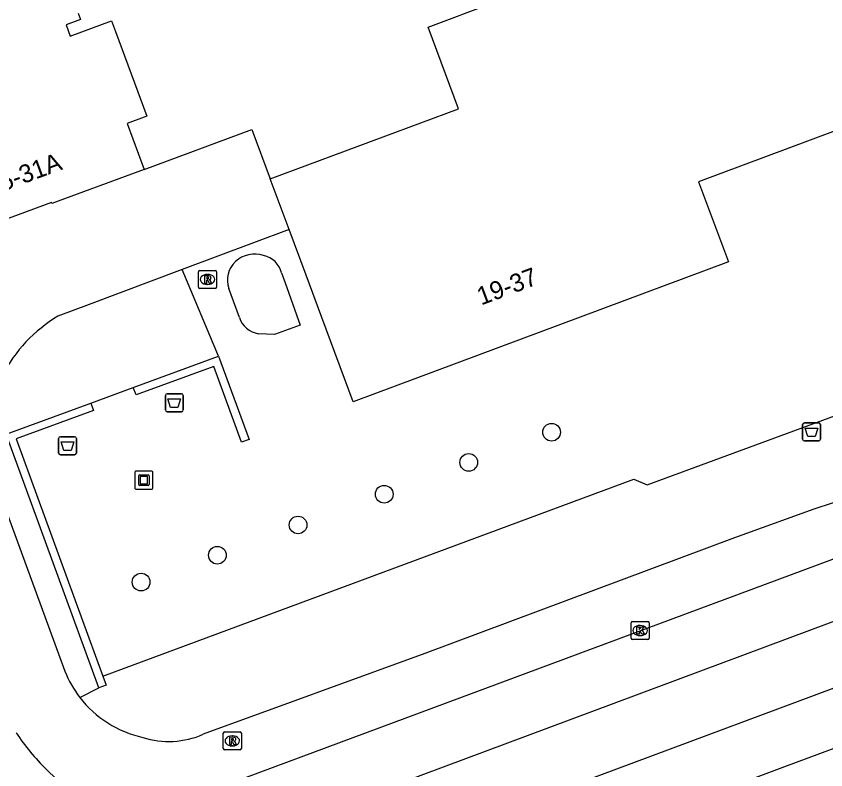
# Model space of a CAD drawing. Extents: x 160806 to 161707, y 383697 to 384148.
# Drawn here: x 161051.44 to 161096.26, y 383880.08 to 383921.78 of the extents above; entities that cross this region are included whole.
import ezdxf

# ---------------------------------------------------------------- set-up
doc = ezdxf.new("R2010")
doc.units = 0
for name, color, linetype in [('IMGEO_Afvalbak', 7, 'Continuous'), ('IMGEO_Boom', 7, 'Continuous'), ('IMGEO_Kolk', 7, 'Continuous'), ('IMGEO_Kunstobject', 7, 'Continuous'), ('IMGEO_Muur', 7, 'Continuous'), ('IMGEO_Pand', 7, 'Continuous'), ('IMGEO_Pand_nummerreeks', 7, 'Continuous'), ('IMGEO_Rijbaan_lokaal_gesloten', 7, 'Continuous'), ('IMGEO_Rijbaan_lokaal_open', 7, 'Continuous'), ('IMGEO_Rioolput', 7, 'Continuous'), ('IMGEO_Voetpad_open', 7, 'Continuous')]:
    doc.layers.add(name, color=color, linetype=linetype)

msp = doc.modelspace()

# ---------------------------------------------------------------- linework, layer by layer
at = {"layer": 'IMGEO_Afvalbak'}
for p, q in [((161059.699, 383899.988), (161059.699, 383900.788)), ((161059.699, 383900.788), (161059.699, 383899.988)), ((161059.799, 383900.888), (161060.589, 383900.888)), ((161060.589, 383900.888), (161059.799, 383900.888)), ((161060.689, 383900.788), (161060.689, 383899.988)), ((161060.689, 383899.988), (161060.689, 383900.788)), ((161060.589, 383899.888), (161059.799, 383899.888)), ((161059.799, 383899.888), (161060.589, 383899.888)), ((161094.972, 383898.377), (161094.972, 383899.177)), ((161094.972, 383899.177), (161094.972, 383898.377)), ((161095.072, 383899.277), (161095.862, 383899.277)), ((161095.862, 383899.277), (161095.072, 383899.277)), ((161095.962, 383899.177), (161095.962, 383898.377)), ((161095.962, 383898.377), (161095.962, 383899.177)), ((161053.788, 383897.607), (161053.788, 383898.407)), ((161053.788, 383898.407), (161053.788, 383897.607)), ((161053.888, 383898.507), (161054.678, 383898.507)), ((161054.678, 383898.507), (161053.888, 383898.507)), ((161054.778, 383898.407), (161054.778, 383897.607)), ((161054.778, 383897.607), (161054.778, 383898.407)), ((161095.862, 383898.277), (161095.072, 383898.277)), ((161095.072, 383898.277), (161095.862, 383898.277)), ((161054.678, 383897.507), (161053.888, 383897.507)), ((161053.888, 383897.507), (161054.678, 383897.507))]:
    msp.add_line(p, q, dxfattribs=at)
for points in [[(161059.842, 383900.602), (161060.546, 383900.602), (161060.397, 383900.132), (161059.991, 383900.132), (161059.842, 383900.602)], [(161095.115, 383898.991), (161095.819, 383898.991), (161095.67, 383898.521), (161095.264, 383898.521), (161095.115, 383898.991)], [(161053.931, 383898.221), (161054.635, 383898.221), (161054.486, 383897.751), (161054.08, 383897.751), (161053.931, 383898.221)]]:
    msp.add_lwpolyline(points, dxfattribs=at)
for centre, start, end in [((161059.799, 383900.788), 90, 180), ((161059.799, 383900.788), 90, 180), ((161060.589, 383900.788), 0, 90), ((161060.589, 383900.788), 360, 90), ((161059.799, 383899.988), 180, 270), ((161059.799, 383899.988), 180, 270), ((161060.589, 383899.988), 270, 0), ((161060.589, 383899.988), 270, 0), ((161095.072, 383899.177), 90, 180), ((161095.072, 383899.177), 90, 180), ((161095.862, 383899.177), 0, 90), ((161095.862, 383899.177), 360, 90), ((161053.888, 383898.407), 90, 180), ((161053.888, 383898.407), 90, 180), ((161054.678, 383898.407), 0, 90), ((161054.678, 383898.407), 360, 90), ((161095.072, 383898.377), 180, 270), ((161095.072, 383898.377), 180, 270), ((161095.862, 383898.377), 270, 0), ((161095.862, 383898.377), 270, 0), ((161053.888, 383897.607), 180, 270), ((161053.888, 383897.607), 180, 270), ((161054.678, 383897.607), 270, 0), ((161054.678, 383897.607), 270, 0)]:
    msp.add_arc(centre, 0.1, start, end, dxfattribs=at)
at = {"layer": 'IMGEO_Boom'}
for centre in [(161081.077, 383898.759), (161076.491, 383897.088), (161071.813, 383895.326), (161067.044, 383893.624), (161062.579, 383891.953), (161058.357, 383890.464)]:
    msp.add_circle(centre, 0.489, dxfattribs=at)
at = {"layer": 'IMGEO_Kolk'}
for p, q in [((161085.476, 383887.357), (161085.476, 383888.209)), ((161085.551, 383888.283), (161086.403, 383888.283)), ((161085.964, 383888.063), (161085.989, 383888.063)), ((161086.477, 383888.209), (161086.477, 383887.357)), ((161085.987, 383887.503), (161085.962, 383887.503)), ((161086.403, 383887.283), (161085.551, 383887.283))]:
    msp.add_line(p, q, dxfattribs=at)
for points in [[(161085.476, 383887.357), (161085.476, 383888.209)], [(161085.551, 383888.283), (161086.403, 383888.283)], [(161085.797, 383887.983), (161085.92, 383887.983), (161085.92, 383887.832), (161086.05, 383887.983), (161086.214, 383887.983), (161086.068, 383887.832), (161086.221, 383887.583), (161086.069, 383887.583), (161085.984, 383887.747), (161085.92, 383887.68), (161085.92, 383887.583), (161085.797, 383887.583), (161085.797, 383887.983)], [(161086.477, 383888.209), (161086.477, 383887.357)], [(161086.403, 383887.283), (161085.551, 383887.283)]]:
    msp.add_lwpolyline(points, dxfattribs=at)
for centre, start, end in [((161085.553, 383888.207), 91.552, 178.448), ((161085.553, 383888.207), 91.552, 178.448), ((161086.401, 383888.207), 1.552, 88.448), ((161086.401, 383888.207), 1.552, 88.448), ((161085.553, 383887.359), 181.552, 268.448), ((161085.553, 383887.359), 181.552, 268.448), ((161086.401, 383887.359), 271.552, 358.448), ((161086.401, 383887.359), 271.552, 358.448)]:
    msp.add_arc(centre, 0.0765, start, end, dxfattribs=at)
for centre, major_axis, ratio, start_param, end_param in [((161085.963, 383887.783), (-0.387, 0.002), 0.722429, 4.712389, 7.853982), ((161085.988, 383887.783), (-0.39, 0.002), 0.717154, 1.570796, 4.712389)]:
    msp.add_ellipse(centre, major_axis=major_axis, ratio=ratio, start_param=start_param, end_param=end_param, dxfattribs=at)
at = {"layer": 'IMGEO_Kunstobject'}
for p, q in [((161058.009, 383896.519), (161058.009, 383895.678)), ((161058.009, 383896.519), (161058.009, 383895.678)), ((161058.925, 383896.603), (161058.084, 383896.603)), ((161058.925, 383896.603), (161058.084, 383896.603)), ((161059.009, 383895.687), (161059.009, 383896.528)), ((161059.009, 383895.687), (161059.009, 383896.528)), ((161058.223, 383895.867), (161058.223, 383896.341)), ((161058.273, 383896.391), (161058.747, 383896.391)), ((161058.303, 383896.291), (161058.303, 383895.917)), ((161058.697, 383896.311), (161058.323, 383896.311)), ((161058.717, 383895.917), (161058.717, 383896.291)), ((161058.797, 383896.341), (161058.797, 383895.867)), ((161058.093, 383895.603), (161058.934, 383895.603)), ((161058.093, 383895.603), (161058.934, 383895.603)), ((161058.747, 383895.817), (161058.273, 383895.817)), ((161058.323, 383895.897), (161058.697, 383895.897))]:
    msp.add_line(p, q, dxfattribs=at)
for centre, radius, start, end in [((161058.087, 383896.525), 0.0779, 92.4484, 184.2845), ((161058.087, 383896.525), 0.0779, 92.4484, 184.2845), ((161058.931, 383896.525), 0.0779, 2.4484, 94.2845), ((161058.931, 383896.525), 0.0779, 2.4484, 94.2845), ((161058.273, 383896.341), 0.05, 90, 180), ((161058.323, 383896.291), 0.02, 90, 180), ((161058.697, 383896.291), 0.02, 360, 90), ((161058.747, 383896.341), 0.05, 360, 90), ((161058.087, 383895.681), 0.0779, 182.4484, 274.2845), ((161058.087, 383895.681), 0.0779, 182.4484, 274.2845), ((161058.273, 383895.867), 0.05, 180, 270), ((161058.323, 383895.917), 0.02, 180, 270), ((161058.697, 383895.917), 0.02, 270, 0), ((161058.747, 383895.867), 0.05, 270, 0), ((161058.931, 383895.681), 0.0779, 272.4484, 4.2845), ((161058.931, 383895.681), 0.0779, 272.4484, 4.2845)]:
    msp.add_arc(centre, radius, start, end, dxfattribs=at)
at = {"layer": 'IMGEO_Muur'}
for points in [[(161057.923, 383901.231), (161062.646, 383902.961)], [(161062.646, 383902.961), (161064.332, 383898.36), (161063.919, 383898.209), (161062.384, 383902.397), (161058.075, 383900.818), (161057.923, 383901.231)], [(161056.013, 383884.618), (161050.88, 383898.651), (161055.575, 383900.371)], [(161055.575, 383900.371), (161055.727, 383899.958), (161051.444, 383898.39), (161056.247, 383885.258)], [(161056.247, 383885.258), (161056.426, 383884.769), (161056.013, 383884.618)]]:
    msp.add_lwpolyline(points, dxfattribs=at)
at = {"layer": 'IMGEO_Pand'}
for points in [[(161104.623, 383923.698), (161106.369, 383919.012), (161089.207, 383912.618), (161090.861, 383908.178), (161083.887, 383905.58), (161070.1, 383900.443), (161068.363, 383905.105), (161067.49, 383907.448), (161066.551, 383909.97)], [(161065.506, 383912.776), (161075.925, 383916.657), (161074.242, 383921.174), (161077.873, 383922.527)], [(161054.873, 383921.943), (161055.004, 383921.59), (161054.205, 383921.295), (161054.435, 383920.674), (161056.726, 383921.521), (161056.943, 383920.935), (161058.676, 383916.245), (161057.594, 383915.845), (161058.534, 383913.302)], [(161058.534, 383913.302), (161053.421, 383911.413), (161053.4, 383911.47), (161049.695, 383910.101), (161043.72, 383907.911), (161043.624, 383908.173)], [(161066.551, 383909.97), (161065.506, 383912.776)], [(161066.13, 383907.574), (161066.324, 383907.033), (161067.169, 383904.68), (161065.737, 383904.17), (161064.847, 383904.207)], [(161063.795, 383905.112), (161063.213, 383906.713)]]:
    msp.add_lwpolyline(points, dxfattribs=at)
for centre, radius, start, end in [((161064.653, 383907.004), 1.61, 72.5301, 132.1393), ((161064.857, 383907.258), 1.312, 13.9277, 77.7092), ((161064.521, 383907.183), 1.389, 133.0557, 199.7632), ((161065.064, 383905.523), 1.334, 197.9557, 260.6357)]:
    msp.add_arc(centre, radius, start, end, dxfattribs=at)
at = {"layer": 'IMGEO_Rijbaan_lokaal_gesloten'}
for points in [[(161058.534, 383913.302), (161064.49, 383915.503), (161065.506, 383912.776)], [(161066.551, 383909.97), (161060.631, 383907.756)], [(161060.631, 383907.756), (161055.478, 383905.83), (161053.746, 383905.182)], [(160964.422, 383835.435), (160992.741, 383845.886), (161007.926, 383851.482), (161013.403, 383853.559), (161017.186, 383855.101), (161020.824, 383856.668), (161025.299, 383858.701), (161029.909, 383860.935), (161036.178, 383864.074), (161039.869, 383865.874), (161048.92, 383870.119), (161052.706, 383871.695), (161058.385, 383874.003), (161123.856, 383898.429)], [(161109.822, 383896.628), (161056.828, 383876.93)], [(161124.834, 383895.166), (161118.453, 383892.804), (161107.78, 383888.735), (161085.608, 383880.466), (161065.062, 383872.804), (161060.248, 383870.877), (161059.167, 383870.205), (161058.026, 383869.524), (161056.736, 383868.572), (161055.15, 383867.42)], [(161053.934, 383850.623), (161053.743, 383851.91), (161053.84, 383854.592), (161054.125, 383856.401), (161054.622, 383858.041), (161055.34, 383859.611), (161057.499, 383862.722), (161060.235, 383865.463), (161062.874, 383867.532), (161065.31, 383869.111), (161066.976, 383870.039), (161069.52, 383871.113), (161073.312, 383872.528), (161077.064, 383873.948), (161084.599, 383876.744), (161093.991, 383880.257), (161106.411, 383884.87), (161115.811, 383888.515)]]:
    msp.add_lwpolyline(points, dxfattribs=at)
msp.add_arc((161058.187, 383897.914), 8.517, 121.4251, 152.0354, dxfattribs=at)
at = {"layer": 'IMGEO_Rijbaan_lokaal_open'}
for points in [[(161050.119, 383896.482), (161054.141, 383885.531)], [(161095.584, 383894.492), (161091.207, 383892.911), (161074.061, 383886.521), (161061.797, 383882.049)]]:
    msp.add_lwpolyline(points, dxfattribs=at)
for centre, radius, start, end in [((161103.929, 383870.979), 24.95, 96.2458, 109.5412), ((161059.773, 383887.776), 6.063, 201.7333, 217.5002), ((161059.739, 383887.759), 6.025, 217.5708, 257.6507), ((161061.78, 383888.939), 12.378, 213.3615, 225.5814), ((161059.896, 383886.293), 4.65, 251.8883, 294.1319), ((161060.199, 383887.11), 9.966, 224.7135, 248.5021)]:
    msp.add_arc(centre, radius, start, end, dxfattribs=at)
at = {"layer": 'IMGEO_Rioolput'}
for p, q in [((161061.531, 383906.788), (161061.531, 383907.64)), ((161061.606, 383907.714), (161062.458, 383907.714)), ((161062.532, 383907.64), (161062.532, 383906.788)), ((161062.019, 383907.494), (161062.044, 383907.494)), ((161062.042, 383906.934), (161062.017, 383906.934)), ((161062.458, 383906.714), (161061.606, 383906.714)), ((161062.905, 383881.25), (161062.905, 383882.102)), ((161062.98, 383882.176), (161063.832, 383882.176)), ((161063.906, 383882.102), (161063.906, 383881.25)), ((161063.393, 383881.956), (161063.418, 383881.956)), ((161063.416, 383881.396), (161063.391, 383881.396)), ((161063.832, 383881.176), (161062.98, 383881.176))]:
    msp.add_line(p, q, dxfattribs=at)
for points in [[(161061.531, 383906.788), (161061.531, 383907.64)], [(161061.606, 383907.714), (161062.458, 383907.714)], [(161062.532, 383907.64), (161062.532, 383906.788)], [(161062.12, 383907.412), (161061.868, 383907.414), (161061.868, 383907.014)], [(161062.046, 383907.333), (161061.992, 383907.333), (161061.992, 383907.252)], [(161061.992, 383907.252), (161062.044, 383907.252)], [(161061.868, 383907.014), (161061.992, 383907.014), (161061.992, 383907.176), (161062.003, 383907.176)], [(161062.05, 383907.147), (161062.121, 383907.014), (161062.261, 383907.014), (161062.196, 383907.14)], [(161062.458, 383906.714), (161061.606, 383906.714)], [(161062.905, 383881.25), (161062.905, 383882.102)], [(161062.98, 383882.176), (161063.832, 383882.176)], [(161063.906, 383882.102), (161063.906, 383881.25)], [(161063.494, 383881.874), (161063.242, 383881.876), (161063.242, 383881.476)], [(161063.42, 383881.795), (161063.366, 383881.795), (161063.366, 383881.714)], [(161063.366, 383881.714), (161063.418, 383881.714)], [(161063.242, 383881.476), (161063.366, 383881.476), (161063.366, 383881.638), (161063.377, 383881.638)], [(161063.424, 383881.609), (161063.495, 383881.476), (161063.635, 383881.476), (161063.57, 383881.602)], [(161063.832, 383881.176), (161062.98, 383881.176)]]:
    msp.add_lwpolyline(points, dxfattribs=at)
for centre, radius, start, end in [((161061.608, 383907.638), 0.0765, 91.552, 178.448), ((161061.608, 383907.638), 0.0765, 91.552, 178.448), ((161062.456, 383907.638), 0.0765, 1.552, 88.448), ((161062.456, 383907.638), 0.0765, 1.552, 88.448), ((161062.028, 383907.441), 0.19, 274.7715, 282.9687), ((161062.052, 383907.237), 0.0964, 77.0061, 93.1865), ((161062.066, 383907.294), 0.0378, 276.6634, 79.6772), ((161062.119, 383907.302), 0.109, 350.3612, 89.416), ((161062.117, 383907.302), 0.112, 277.5842, 350.9817), ((161062.101, 383907.087), 0.108, 29.5134, 73.7905), ((161061.608, 383906.79), 0.0765, 181.552, 268.448), ((161061.608, 383906.79), 0.0765, 181.552, 268.448), ((161062.002, 383907.123), 0.0533, 26.0293, 88.6989), ((161062.456, 383906.79), 0.0765, 271.552, 358.448), ((161062.456, 383906.79), 0.0765, 271.552, 358.448), ((161062.982, 383882.1), 0.0765, 91.552, 178.448), ((161062.982, 383882.1), 0.0765, 91.552, 178.448), ((161063.83, 383882.1), 0.0765, 1.552, 88.448), ((161063.83, 383882.1), 0.0765, 1.552, 88.448), ((161063.402, 383881.903), 0.19, 274.7715, 282.9687), ((161063.426, 383881.699), 0.0964, 77.0061, 93.1865), ((161063.44, 383881.756), 0.0378, 276.6634, 79.6772), ((161063.493, 383881.764), 0.109, 350.3612, 89.416), ((161063.491, 383881.764), 0.112, 277.5842, 350.9817), ((161063.475, 383881.549), 0.108, 29.5134, 73.7905), ((161062.982, 383881.252), 0.0765, 181.552, 268.448), ((161062.982, 383881.252), 0.0765, 181.552, 268.448), ((161063.376, 383881.585), 0.0533, 26.0293, 88.6989), ((161063.83, 383881.252), 0.0765, 271.552, 358.448), ((161063.83, 383881.252), 0.0765, 271.552, 358.448)]:
    msp.add_arc(centre, radius, start, end, dxfattribs=at)
for centre, major_axis, ratio, start_param, end_param in [((161062.018, 383907.214), (-0.387, 0.002), 0.722429, 4.712389, 7.853982), ((161062.043, 383907.214), (-0.39, 0.002), 0.717154, 1.570796, 4.712389), ((161063.392, 383881.676), (-0.387, 0.002), 0.722429, 4.712389, 7.853982), ((161063.417, 383881.676), (-0.39, 0.002), 0.717154, 1.570796, 4.712389)]:
    msp.add_ellipse(centre, major_axis=major_axis, ratio=ratio, start_param=start_param, end_param=end_param, dxfattribs=at)
at = {"layer": 'IMGEO_Voetpad_open'}
for points in [[(161056.247, 383885.258), (161085.633, 383896.162), (161086.368, 383895.852), (161097.15, 383899.812), (161099.69, 383905.487), (161096.881, 383913.365), (161111.083, 383918.654), (161110.447, 383920.534), (161114.626, 383922.225)], [(161062.646, 383902.961), (161060.631, 383907.756)], [(161055.575, 383900.371), (161057.923, 383901.231)], [(161054.963, 383884.085), (161056.013, 383884.618)]]:
    msp.add_lwpolyline(points, dxfattribs=at)

# ---------------------------------------------------------------- texts
at = {"layer": 'IMGEO_Pand_nummerreeks'}
for s, rotation, p in [('31-31/01-31/15-31A', 20.277, (161042.899, 383909.19)), ('19-37', 20.4341, (161077.178, 383905.769))]:
    msp.add_text(s, height=1, rotation=rotation, dxfattribs=at).set_placement(p)

doc.saveas('drawing.dxf')
